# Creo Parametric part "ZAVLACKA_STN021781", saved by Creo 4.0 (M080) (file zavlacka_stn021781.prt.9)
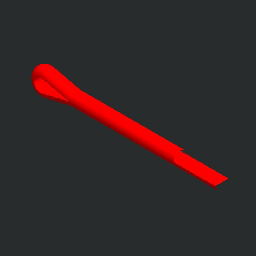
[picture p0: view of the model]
Units: Custom; MM, KILOGRAM, SECS
Materials in the file: OCEL_N

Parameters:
  MFG_WP_MATERIAL = "OCEL"
  NAZOV = "ZAVLACKA_STN021781"
  NORMA = "STN 02 1781"
  PTC_MATERIAL_NAME = "OCEL_N"

Other parameters: HMOTNOST, HUSTOTA, D4, D9

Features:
  1. datum plane "DTM1"
  2. datum axis
  3. datum plane "DTM2"

Layers: 1, 2, 3, 4, 5, 6, 7, 8, 9, 10, 11, 12, 13, 14, 15, 16, 17, 18, 19, 20, 21, 22, 23, 24, 25, 26, 27, 28, 29, 30, 31, 32

Family table entries: GENERIC, ZAVLACKA_0_6, ZAVLACKA_STN021781, value(d_val), value(i_val), ZAVLACKA_0_8, ZAVLACKA_STN021781, ZAVLACKA_1, ZAVLACKA_STN021781, ZAVLACKA_1_2, ZAVLACKA_STN021781, ZAVLACKA_1_6, ZAVLACKA_STN021781, ZAVLACKA_2, ZAVLACKA_STN021781, ZAVLACKA_2_5, ZAVLACKA_STN021781, ZAVLACKA_3_2, ZAVLACKA_STN021781, ZAVLACKA_4, ZAVLACKA_STN021781, ZAVLACKA_5, ZAVLACKA_STN021781, ZAVLACKA_6_3, ZAVLACKA_STN021781, ZAVLACKA_8, ZAVLACKA_STN021781, 2/!, 2/., ZAVLACKA_10, ZAVLACKA_STN021781, !/#, 2/%, 2/3, ZAVLACKA_13, ZAVLACKA_STN021781, ZAVLACKA_16, ZAVLACKA_STN021781, ZAVLACKA_20, ZAVLACKA_STN021781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

Surfaces: 6 plane, 5 cylinder, 1 torus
